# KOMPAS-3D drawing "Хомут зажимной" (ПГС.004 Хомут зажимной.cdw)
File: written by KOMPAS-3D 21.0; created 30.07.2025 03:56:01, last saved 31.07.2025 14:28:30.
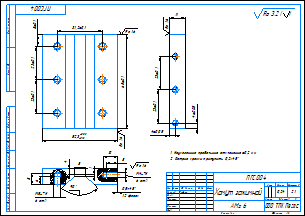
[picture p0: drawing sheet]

Sheet 1: A3, landscape

Document properties: Автор: rinat.gaysin.00@bk.ru; Полное имя файла: C:\Users\User\Desktop\ПЕРСПЕКТИВА кд\Чертежи\ПГС.004 Хомут зажимной.cdw; Знак неуказанной шероховатости: 4; Параметр неуказанной шероховатости: Ra 3.2; Масса: 0.237292

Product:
- Part/product: Хомут зажимной
    Масса: 0.237292
    Форматы листов документа: A3

Title block, sheet 1: Наименование: Хомут зажимной; designation: ПГС.004; Материал: АМг 6; Масса: 0,24; Количество листов документа: 1; organisation: ООО ТПК Пегас; Форматы листов документа: A3; stored path: C:\Users\User\Desktop\ПЕРСПЕКТИВА кд\Чертежи\Хомут зажимной.cdw; Разработал: Гайсин

Views: Вид 1, Спереди, Проекционный вид 2, Проекционный вид 3, Местный разрез 1, Местный разрез 2
Referenced files in C:\Users\rinat\OneDrive\Рабочий стол\ПЕРСПЕКТИВА кд\Модель\: Хомут зажимной.m3d
Referenced files in C:\Users\User\Desktop\ПЕРСПЕКТИВА кд\Модель\: ПГС.004 Хомут зажимной.m3d
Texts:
  Ra 1.6
  Ra 3.2
  Ra 3.2 ( )
Dimensions and other numbers on the sheet: 31,2±0,1; 23±0,1; 8±0,1; 65±0,1; 52,3; 9; 4±0,05; 11; 1; 6; 6 отв; 10; 0,5; 12 фасок; 2:1; 0,24

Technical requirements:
  Неуказанные предельные отклонения  0,2 мм
  Острые кромки притупить 0,2х45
